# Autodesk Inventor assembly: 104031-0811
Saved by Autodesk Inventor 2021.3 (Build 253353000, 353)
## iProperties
Created: 2022-06
Part Number: 104031-0811
Document SubType Name: Assembly
Designer: Administrator
Title: 104031-0811
Author: Administrator
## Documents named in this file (2)
- c:\worker\convert-fusion-r03\tmp\job-1\203\output\files\98ba3c1f-9f0e-47fe-8659-38db50984f0d\104031-0811.iam
- c:\worker\convert-fusion-r03\tmp\job-1\203\output\files\98ba3c1f-9f0e-47fe-8659-38db50984f0d\COMPOUND (4).ipt
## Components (1 placed, 1 different names)
1. COMPOUND (4):1
